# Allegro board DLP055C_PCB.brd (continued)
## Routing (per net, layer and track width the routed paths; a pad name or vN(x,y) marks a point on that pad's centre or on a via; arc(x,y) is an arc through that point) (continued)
P5V: length 223.8
  TOP w0.254: v1(177.87,5.34) 177.91,5.38 J28.1
  TOP w0.635: TP232.1 83.64,33.36 ; TP232.1 82.57,33.36 ; TP232.1 83.64,34.43 ; TP232.1 82.57,34.43
  LY3 w0.381: v1(177.91,4.49) 177.93,4.49 180.03,6.59 180.03,8.75 185.44,14.16 185.44,33.46 184.17,34.73 184.17,41.66 185.44,42.93 185.44,87.04 185.47,87.07 185.47,94.65 184.81,95.31 184.81,133.92 182.37,136.36 182.37,141.64 178.05,145.96 154.63,145.96 153.23,144.56 149.35,144.56 145.23,148.68 135.07,148.68 131.77,145.37 131.77,140.34 J67.1
  LY7_PLANE w0.635: J67.1 132.66,141.23 ; J67.1 132.66,139.44 ; J67.1 130.87,141.23 ; J67.1 130.87,139.44
  BOTTOM w0.381: C507.2 177.6,5.69 177.91,5.38 v1(177.87,5.34)
  BOTTOM w0.635: J60.1 129.15,9.6 ; J60.1 126.76,11.99 ; J60.1 129.15,11.99 ; J60.1 126.76,9.6 ; 82.57,33.36 TP232.1 ; TP232.1 82.57,34.43 ; TP232.1 83.64,33.36 ; TP232.1 83.64,34.43
  vias: v1(82.5,32.95) v1(83.77,32.95)
P5V_FP_FE: length 2.5
  TOP w0.445: 129.6,9.9 J60.2 131.39,9.9
P5V_VX1_FE: length 5.1
  TOP w0.445: 128.33,139.44 J67.2 ; J67.2 130.12,139.44 ; J67.2 130.12,141.23 ; J67.2 128.33,141.23
P12V: length 91.1
  TOP w0.381: 173.44,143.19 173.44,142.52 173.82,142.14 v1(174.47,142.14) ; 173.44,143.19 C1.1 ; 173.44,143.19 v1(174.47,143.19) ; 173.44,143.19 173.44,143.84 173.82,144.22 v1(174.47,144.22) ; 173.44,132.4 173.44,131.72 173.82,131.34 v1(174.47,131.34) ; 173.44,132.4 v1(174.47,132.4) ; 173.44,132.4 173.44,133.05 173.82,133.43 v1(174.47,133.43) ; 173.44,132.4 C8.1 172.71,132.4 172.26,132.85 170.63,132.85 169.34,131.56 169.34,130.41 168.15,129.22 R246.1 ; v1(139.09,41.91) R80.2 140.34,40.8 v1(140.41,40.73) ; v1(146.42,55.05) 145.75,54.38 J114.1
  LY7_PLANE w0.635: 172.26,136.38 J5.1 ; J5.1 174.45,138.57 ; J5.1 172.26,138.57 ; J5.1 174.45,136.38 ; 182.74,139.24 J8.1 ; J8.1 184.93,139.24 ; J8.1 184.93,141.43 ; J8.1 182.74,141.43 ; 172.26,147.18 J4.1 ; J4.1 174.45,149.37 ; J4.1 172.26,149.37 ; J4.1 174.45,147.18
  BOTTOM w0.254: U59.5 65.02,122.83 ; U59.3 65.24,123.83 ; U59.4 65.28,123.32
  BOTTOM w0.381: C71.1 183.2,140.97 J8.1 ; 147.76,53.97 147.65,53.86 C830.2 144.35,53.86 144.21,53.72
  BOTTOM w0.635: 137.63,51.68 J97.2 136.05,51.68 ; 77.15,140.46 TP247.1 ; TP247.1 78.22,140.46 ; TP247.1 77.15,139.39 ; C803.1 71.46,133.5 ; C803.1 71.46,130.66 ; C803.1 69.94,132.08 ; C803.1 72.99,132.08 ; 101.51,25.09 J120.2 ; 99.07,25.09 J120.1 99.07,26.98 ; 120.66,25.73 J121.1 120.66,27.61 ; C805.1 79.06,132.94 ; C805.1 79.06,129.9 ; C805.1 80.48,131.42 ; C805.1 77.63,131.42 ; C804.1 80.96,129.18 ; C804.1 82.39,127.66 ; C804.1 80.96,126.14 ; C804.1 79.54,127.66 ; C802.1 73.34,128.55 ; C802.1 74.77,127.03 ; C802.1 71.92,127.03 ; C802.1 73.34,125.5 ; 68.11,136.5 C58.1 ; C58.1 69.53,134.98 ; C58.1 69.53,138.02 ; C58.1 70.96,136.5 ; 123.1,25.73 J121.2
  vias: v1(74.13,132.89) v1(74.18,131.9) v1(75.73,132.82) v1(75.65,131.88) v1(150.18,147.95) v1(150.18,146.69) v1(150.18,145.41) v1(151.45,147.95) v1(151.45,146.69) v1(151.45,145.41) v1(152.72,147.95) v1(152.72,146.69) v1(152.72,145.41) v1(155.74,54.13) v1(156.79,54.21) v1(157.8,54.16) v1(158.79,54.13)
P12V_CNTL_D: length 7.8
  TOP w0.191: v1(61.39,133.84) 60.9,133.35 R825.1
  BOTTOM w0.191: v1(61.39,133.84) 61.33,133.78 R826.2 58.15,133.78 57.7,134.22 57.7,136.47 Q13.3
P12V_CNTL_G: length 29.3
  TOP w0.191: C809.2 52.24,138.49 v1(52.24,139.56) 52.18,139.62 R830.1 ; SW5.1 51.72,143.51 52.12,143.11 52.12,141.04 R830.1 ; R830.1 R824.1
  LY3 w0.122: v1(52.24,139.56) 48.59,135.9 v1(42.82,135.9)
  BOTTOM w0.191: D51.3 43.29,135.43 v1(42.82,135.9) ; D50.2 51.43,138.74 v1(52.24,139.56) 52.91,138.89 Q13.1
P12V_DLPA100: length 150.7
  TOP w0.203: v1(61.2,58.01) 61.28,58.01 61.49,57.8 U555.9 ; v1(69.89,99.79) 69.96,99.71 U557.9 ; U557.22 78.27,95.18 78.41,95.05 v1(78.41,94.98) ; U557.37 v1(80.01,105.41) ; v1(82.65,99.16) 82.36,99.16 82.3,99.21 U557.27 ; U555.22 69.38,53.72 69.39,53.71 69.39,52.72 69.38,52.71 69.38,52.16 69.1,51.88 v1(69.1,50.23) ; U555.27 v1(73.54,57.3) ; U556.42 28.44,55.95 28.44,56.77 28.32,56.89 28.32,57.56 v1(28.14,57.74) ; v1(22.26,50.47) 22.55,50.18 U556.9 ; U556.37 v1(31.81,55.88) ; v1(68.25,65.67) 67.88,65.3 67.88,65.13 67.87,65.12 67.87,64.7 67.88,64.69 U555.42 ; U557.42 76.77,106.57 v1(76.5,106.84) ; U555.37 v1(71.08,63.5)
  TOP w0.254: U556.22 v1(30.01,45.51) ; U556.27 v1(34,49.68)
  TOP w0.381: v1(69.1,50.23) 67.03,48.16 C752.2 ; DN7.2 v1(25.72,29.67) ; R781.2 32.82,42.48 v1(32.15,42.48) ; DN5.2 v1(28.89,29.67) ; R800.1 v1(87.65,98.99) ; R803.1 v1(66.29,105.34) ; DN8.2 v1(35.24,29.67) ; v1(84.93,94.4) 84.37,94.4 R802.2 ; DN2.2 v1(59.25,35.97) ; DN3.2 v1(45.59,36.36) ; DN4.2 v1(59.25,40.49) ; DN6.2 v1(32.07,29.67) ; v1(31.1,45.31) 31.1,44.3 C773.2 ; DN11.2 v1(73.63,91.12) ; C787.2 v1(80.24,91.82) ; DN1.2 v1(55.44,35.97)
  BOTTOM w0.254: U59.8 59.91,123.83 ; U59.6 59.69,122.83 ; U59.7 59.57,123.32
  BOTTOM w0.381: v1(28.14,57.74) 28.22,57.67 28.22,56.24 28.57,55.89 C774.2 ; R739.2 v1(81.13,55.51) ; v1(22.26,50.47) 22.65,50.09 C775.2 ; v1(76.5,106.84) 76.5,105.71 C789.2 ; C753.2 69.51,65.36 68.96,65.36 68.65,65.67 v1(68.25,65.67) ; C776.2 30.08,45.58 v1(30.01,45.51) ; v1(78.41,94.98) 78.66,94.98 78.74,95.06 C788.2
  BOTTOM w0.635: 49.07,35.11 TP249.1 ; TP249.1 49.07,36.18 ; TP249.1 50.14,35.11 ; TP249.1 50.14,36.18 ; 78.02,109.05 R801.1 ; R801.1 78.02,110.27 ; R801.1 77.29,109.66 ; R801.1 78.76,109.66 ; DN12.2 64.45,88.61 ; DN12.2 63.87,87.95 ; DN12.2 64.45,87.29 ; DN10.2 67.63,88.61 ; DN10.2 67.04,87.95 ; DN10.2 67.63,87.29 ; 57.47,128.73 C828.2 ; C828.2 57.47,129.95 ; C828.2 58.2,129.34 ; C828.2 56.73,129.34 ; C829.2 58.1,120.19 ; C829.2 58.84,119.58 ; C829.2 57.37,119.58 ; C829.2 58.1,118.97 ; 32.7,46.81 R779.1 ; R779.1 33.44,47.42 ; R779.1 32.7,48.03 ; R779.1 31.97,47.42 ; R782.1 27.72,60.53 ; R782.1 26.99,61.14 ; R782.1 26.99,59.92 ; R782.1 26.25,60.53 ; C823.1 61.43,99.09 ; C823.1 58.58,99.09 ; C823.1 60.01,97.56 ; 70.9,64.95 C753.2 69.92,64.07 ; 54.32,123.04 C824.1 ; C824.1 54.32,125.88 ; C824.1 52.79,124.46 ; C824.1 55.84,124.46 ; R780.1 29.63,60.53 ; R780.1 28.89,61.14 ; R780.1 28.89,59.92 ; R780.1 28.16,60.53 ; 61.1,127 C827.2 ; C827.2 62.32,127 ; C827.2 61.71,127.74 ; C827.2 61.71,126.26 ; DN9.2 70.8,88.61 ; DN9.2 70.8,87.29 ; DN9.2 70.22,87.95 ; 67,49.02 C755.2 ; C755.2 67.98,49.9 ; C755.2 68.96,49.02 ; C754.2 73.67,55.54 ; C754.2 72.69,56.42 ; C754.2 71.71,55.54 ; 66.36,97.56 C826.1 ; C826.1 64.93,99.09 ; C826.1 66.36,100.61 ; C826.1 67.78,99.09 ; 37.7,49.42 R778.2 ; R778.2 38.58,50.4 ; R778.2 37.7,51.38 ; 52.79,119.13 C821.1 ; C821.1 55.84,119.13 ; C821.1 54.32,117.7 ; C821.1 54.32,120.55 ; C775.2 25.03,50.09 ; 70.78,114.78 C825.1 ; C825.1 69.25,116.2 ; C825.1 70.78,117.63 ; C825.1 72.3,116.2 ; 30.08,48.21 C776.2 30.96,47.23 ; 78.74,97.5 C788.2 77.87,96.52 ; 85.83,100.15 R799.2 85.83,102.1 ; 81.13,57.82 R739.2 82,56.85 ; 52.79,129.79 C822.1 ; C822.1 55.84,129.79 ; C822.1 54.32,131.22 ; C822.1 54.32,128.37 ; 29.45,55.88 C774.2 28.57,54.9 ; C790.2 81.91,99.38 ; C790.2 80.93,98.5 ; C790.2 79.95,99.38 ; 77.68,105.41 C789.2 76.8,104.43
P12V_DRV: length 6
  TOP w0.381: U35.12 144.28,43.82 v1(144.11,43.99) 142.74,43.99 C133.1 R80.1
  BOTTOM w0.381: C320.1 144.87,43.84 144.26,43.84 v1(144.11,43.99)
P12V_REF: length 4.7
  TOP w0.191: v1(49.42,139.74) R823.1
  BOTTOM w0.191: D50.1 49.53,139.63 v1(49.42,139.74) R829.2
P12V_SEQ_EN: length 28
  LY3 w0.122: v1(66.45,124.04) 69.42,121.07 70.28,121.07 71.42,119.92 71.42,118.14 74.94,114.62 79.75,114.62 v1(80.65,113.72)
  BOTTOM w0.191: U58.4 v1(80.65,113.72) ; U59.2 64.7,124.33 64.99,124.61 65.87,124.61 v1(66.45,124.04) 66.46,124.03 R198.2
P12V_SW_G: length 9.7
  TOP w0.191: D49.1 58.56,133.38 R825.2 ; R825.2 R822.1 ; R825.2 58.53,132.13 57.7,131.3 57.7,129.99 Q12.G
P12V_VIN: length 30.9
  TOP w0.445: 43.57,129.62 J528.1 45.96,129.62 ; 42.79,129.62 J527.1 40.4,129.62 ; 66.46,119.92 TP245.1
  LY8_PLANE w0.376: J527.1 42.49,129.91 ; J527.1 40.7,131.71 ; J527.1 40.7,129.91 ; J527.1 42.49,131.71 ; J528.1 45.66,129.91 ; J528.1 43.87,131.71 ; J528.1 43.87,129.91 ; J528.1 45.66,131.71 ; TP245.1 67.53,118.84 ; TP245.1 67.53,119.92 ; TP245.1 66.46,119.92 ; TP245.1 66.46,118.84
  BOTTOM w0.381: U524.8 169.73,143.21 C811.2 172.33,143.08 C810.2 v1(172.4,144.45) ; R833.2 v1(171.97,132.16)
  BOTTOM w1.016: J527.1 J528.1
VBUS: length 13.6
  TOP w0.191: TP76.1 39.86,105.88 37.94,105.88 37.38,106.43 37.38,110.4 34.33,113.45 U26.65
VDD33_FPD: length 25.5
  TOP w0.305: v1(146.61,95.26) 146.51,95.26 145.46,94.22 145.46,88.12 145.84,87.74 145.84,86.22 145.97,86.09 146.26,86.09 v1(146.45,85.9) U15.L13
  TOP w0.381: U15.E14 v1(140.45,86.9) ; U15.E6 v1(140.45,78.9) ; U15.G6 v1(142.45,78.9) ; U15.E8 v1(140.45,80.9) ; U15.E12 v1(140.45,84.9) ; U15.E10 v1(140.45,82.9) ; U15.L11 v1(146.45,83.9)
  BOTTOM w0.305: L506.2 143.16,79.61 v1(142.45,78.9) C287.1 ; v1(140.45,80.9) C267.1 ; v1(140.45,86.9) C230.1 ; v1(140.45,82.9) C266.1 ; v1(140.45,84.9) C265.1 ; C289.1 v1(140.45,78.9) U15.E6 ; C170.2 v1(146.61,95.26) ; v1(146.45,85.9) C255.1
  BOTTOM w0.381: v1(146.45,83.9) C258.1
VDD115_FPD: length 35.8
  TOP w0.381: U15.J6 v1(144.45,78.9) ; v1(141.45,83.9) U15.F11 142.47,83.88 142.47,82.92 ; 142.47,82.92 142.48,82.92 142.95,82.46 144.01,82.46 v1(146.45,84.9) U15.L12 ; 142.47,82.92 U15.F9 v1(141.45,81.9) ; U15.F7 v1(141.45,79.9)
  LY3 w0.381: 142.19,79.9 v1(141.45,79.9) ; 142.19,79.9 142.32,79.77 143.58,79.77 v1(144.45,78.9) 146.76,81.21 v1(146.76,82.05) ; 142.19,79.9 142.19,81.16 v1(141.45,81.9)
  LY12 w0.229: 141.95,79.4 141.95,73.43
  LY12 w0.254: v1(142.04,72.05) 142.04,73.34 141.95,73.43 ; v1(141.45,79.9) 141.95,79.4
  BOTTOM w0.305: v1(141.45,81.9) C262.1 ; v1(146.45,84.9) C257.1 ; v1(141.45,79.9) C264.1 ; v1(141.45,83.9) C263.1 ; v1(146.76,82.05) C259.2 146.44,80.7 C284.1 ; C286.1 v1(144.45,78.9)
  BOTTOM w0.381: L505.1 v1(142.04,72.05)
VDD115_HSSI0_PLL: length 3.1
  TOP w0.191: U15.AE22 v1(161.45,95.9)
  BOTTOM w0.381: C155.1 v1(161.45,95.9) C159.1 L13.1
VDD115_HSSI1_PLL: length 3.4
  TOP w0.191: U15.AE10 v1(161.45,82.9)
  BOTTOM w0.381: L24.1 C239.1 C236.1 v1(161.45,82.9)
VDD115_PLLMA: length 3.4
  TOP w0.191: U15.AE18 v1(161.45,91.9)
  BOTTOM w0.381: v1(161.45,91.9) U15.AE18 C182.1 L16.1
VDD115_PLLMB: length 3.1
  TOP w0.191: U15.F15 v1(141.45,87.9)
  BOTTOM w0.381: C224.1 U15.F15 v1(141.45,87.9) C228.1
VDD115_PLLS: length 3.2
  TOP w0.191: U15.F16 v1(141.45,89.9)
  BOTTOM w0.305: C226.1 140.86,89.32 140.03,89.32 C229.1
  BOTTOM w0.381: L21.1 v1(141.45,89.9) C226.1
3D_LR: length 7.9
  TOP w0.191: J62.1 119.7,20.95 TP212.1 J61.2
3D_REF: length 142.7
  TOP w0.191: J44.3 89.15,8.65 89.15,8.65 89.15,9.07 89.15,9.07 v1(89.15,9.45)
  TOP w0.381: U15.D15 v1(139.45,87.9)
  LY3 w0.076: 137.3,88.52 137.09,88.52 137.08,88.53 136.93,88.53 136.93,88.52 136.65,88.52 136.62,88.49 136.28,88.49 136.24,88.52 135.99,88.52
  LY3 w0.102: v1(139.45,87.9) 139.45,87.96 138.89,88.52 137.3,88.52 ; 135.99,88.52 135.88,88.64
  LY3 w0.122: v1(91.26,87.45) 91.32,87.45 92.89,89.02 92.89,89.15 94.7,90.96 105.57,90.96 105.94,90.59 110.13,90.59 110.51,90.98 110.52,90.98 111.83,92.29 119.5,92.29 121.38,90.41 124.75,90.41 126.35,88.81 135.71,88.81 135.88,88.64
  LY12 w0.122: v1(91.26,87.45) 91.79,86.92 91.79,62.98 98.07,56.7 98.07,54.19 88.97,45.09 88.97,29.3 89.19,29.08 89.19,19.85 86.92,17.58 86.92,13.54 87.52,12.94 88.67,12.94 89.68,11.93 89.68,9.99 v1(89.15,9.45)
38MHZ_I: length 6.8
  BOTTOM w0.191: R118.1 C232.2 133.78,86.16 132.99,85.36 131.17,85.36 130.6,85.94 X2.1
38MHZ_O: length 3.9
  BOTTOM w0.191: X2.3 133.63,89.37 R117.1 133.78,89.96 C231.2
40MHZ_CLK0: length 227.2
  TOP w0.185: J500.26 v1(59.37,9.8)
  LY3 w0.122: v1(59.37,9.8) 59.37,7.28 60.07,6.59 75.59,6.59 76.91,5.27 134.16,5.27 136.75,7.86 136.75,12.11 137.54,12.9 137.54,15.02 138.53,16.01 138.53,17.26 144.67,23.4 154.53,23.4 156.76,21.17 170.56,21.17 174.93,25.54 174.93,27.69 176.5,29.27 176.5,30.44 182.39,36.33 182.39,43.16 184.93,45.7 184.93,86.23 185.02,86.32 185.02,88.95 v1(184.45,89.52)
  BOTTOM w0.191: R706.1 173.56,96.68 174.4,97.52 182.44,97.52 183.28,96.68 183.28,93.38 182.45,92.54 R669.2 182.45,89.49 182.8,89.14 184.07,89.14 v1(184.45,89.52)
40MHZ_I: length 2.5
  TOP w0.191: R30.1 C69.2 171.72,93.34 X1.1
40MHZ_O: length 6.1
  TOP w0.191: R31.1 C70.2 170.38,89.97 170.98,89.37 172.87,89.37 173.57,90.07 X1.3
40MHZ_Y0: length 2.7
  BOTTOM w0.191: R669.1 181.41,89.64 180.64,90.41 179.25,90.41 U503.3
40MHZ_Y1: length 4.3
  BOTTOM w0.191: R656.1 R655.1 171.58,92.08 171.88,91.78 U503.8
ACT_A_CIPO: length 22
  TOP w0.191: U51.3 123.2,29.16 123.06,29.02 119.3,29.02 118.99,28.7 118.97,28.7 118.95,28.69 107.16,28.69 J120.4
ACT_A_CLK: length 21.3
  TOP w0.191: J120.5 108.31,28.34 119.1,28.34 119.11,28.36 119.13,28.36 119.44,28.67 123.2,28.67 123.21,28.69 123.31,28.69 124.2,29.57 U51.5
ACT_A_COPI: length 22.6
  TOP w0.191: U51.2 122.7,29.87 122.36,29.52 119.32,29.52 118.84,29.04 106.02,29.04 J120.3
ACT_B_CIPO: length 18.7
  TOP w0.191: J120.8 112.12,27.66 119.38,27.66 119.39,27.67 119.41,27.67 119.73,27.99 123.49,27.99 123.5,28 123.6,28 123.61,28.01 124.12,28.01 124.13,28.03 124.79,28.03 125.7,28.94 U51.8
ACT_B_CLK: length 17.8
  TOP w0.191: J120.9 113.28,27.31 119.52,27.31 119.54,27.33 119.55,27.33 119.87,27.64 123.63,27.64 123.64,27.66 123.74,27.66 123.75,27.67 124.26,27.67 124.27,27.68 124.93,27.68 124.94,27.69 125.16,27.69 126.2,28.74 U51.9
ACT_B_COPI: length 19.1
  TOP w0.191: J120.7 110.97,28 119.24,28 119.25,28.01 119.27,28.01 119.59,28.33 123.34,28.33 123.36,28.34 123.46,28.34 123.47,28.36 123.97,28.36 124.7,29.08 124.7,29.38 124.68,29.4 124.68,29.82 124.7,29.84 U51.6
ACT_C_CIPO: length 5.2
  TOP w0.191: J121.4 127.7,28.27 U51.12
ACT_C_CLK: length 4.8
  TOP w0.191: U51.13 128.2,27.28 J121.5
ACT_C_COPI: length 5.6
  TOP w0.191: J121.3 125.28,27.35 125.3,27.35 126.55,28.6 126.55,28.62 127.2,29.27 U51.11
ACT_D_CIPO: length 5.5
  TOP w0.191: U51.16 129.7,29.06 J121.8
ACT_D_CLK: length 6.4
  TOP w0.191: U51.17 130.2,29.89 130.2,29.89 130.2,29.47 130.2,29.47 130.2,29.24 131.01,28.43 131.83,28.43 J121.9
ACT_D_COPI: length 5.3
  TOP w0.191: J121.7 128.7,28.56 U51.14
AFE_ARSTZ: length 124.5
  TOP w0.191: v1(113.69,9.65) 112.36,9.65 112.1,9.4 111.39,9.4 111.15,9.15 111.15,9.07 111.15,9.07 111.15,8.66 111.15,8.65 J44.47 ; v1(123.97,72.2) 124.76,71.41 126.74,71.41 127.4,72.07 132.36,72.07 133.03,72.74 138.34,72.74 138.49,72.89 141.09,72.89 141.54,73.34 144.98,73.34 145.49,73.85 145.49,74.91 145.95,75.37 U15.K2
  LY12 w0.122: v1(113.69,9.65) 113.69,11.72 113.18,12.23 110.38,12.23 109.52,13.09 109.52,15.66 108.12,17.06 99.82,17.06 98.24,18.63 98.24,28.08 102.34,32.17 102.34,55.88 104.67,58.22 107.12,58.22 108.27,59.37 108.27,69.65 109.77,71.15 119.06,71.15 120.55,72.63 122.8,72.63 123.23,72.2 v1(123.97,72.2)
AFE_CLK: length 101.1
  TOP w0.185: J44.44 109.65,9.25 109.94,9.55
  TOP w0.191: 109.94,9.55 110.25,9.55 v1(110.35,9.65) ; R626.2 v1(142.43,64.94)
  LY5 w0.122: v1(142.43,64.94) 143.15,64.22 145.59,64.22 148,61.81 148,56.6 150.19,54.42 152.4,54.42 154.59,52.23 154.59,31.23 150.9,27.54 143.07,27.54 134.16,18.63 117.67,18.63 115.97,16.93 113.71,16.93 112.11,15.32 112.11,12.81 111.81,12.51 111.81,10.17 111.29,9.65 v1(110.35,9.65)
AFE_CLK_T: length 13.1
  TOP w0.191: v1(142.32,65.85) 142.18,65.99 R626.1 ; U15.K3 v1(145.45,75.9)
  LY12 w0.122: v1(142.32,65.85) 142.41,65.95 142.41,66 143.43,67.01 143.43,70.16 145.13,71.87 145.13,72.91 145.44,73.21 145.44,75.89 v1(145.45,75.9)
AFE_IRQ: length 92.8
  TOP w0.191: R627.1 158.43,15.33 155.9,17.87 143.2,17.87 v1(142.82,17.48)
  TOP w0.381: U15.K4 v1(145.45,76.9)
  LY12 w0.122: v1(142.82,17.48) 142.82,22.43 151.38,31 151.38,36.64 150.87,37.14 146.83,37.14 145.99,37.99 145.99,39.62 145.73,39.87 142.55,39.87 142.09,40.33 142.09,41 142.4,41.31 142.4,41.88 140.84,43.44 140.84,48.83 140.82,48.85 140.82,52.75 140.84,52.77 140.84,60.59 141.23,60.98 141.23,65.66 142.59,67.01 142.59,69.76 144.04,71.21 144.04,72.73 144.98,73.67 144.98,76.44 145.44,76.9 v1(145.45,76.9)
AISEN: length 2.7
  TOP w0.191: U35.3 152.38,42.52 152.38,42.52 v1(152.46,42.52)
  BOTTOM w0.191: v1(152.46,42.52) 151.36,42.52 R144.1
ALF_CSYNC: length 111.3
  TOP w0.191: J44.42 108.61,7.64 108.61,9.26 109.36,10.01 109.94,10.01 110.73,10.79 TP51.1
  TOP w0.381: U15.J2 v1(144.45,74.9)
  LY5 w0.122: v1(144.45,74.9) 145.07,74.28 145.07,71.88 143.61,70.43 143.61,68.4 142.4,67.19 142.26,67.19 141.83,66.76 141.83,63.94 144.27,61.5 145,61.5 147.52,58.99 147.52,56.45 150.36,53.6 152.29,53.6 154.29,51.61 154.29,31.72 150.57,28 143.02,28 134.31,19.29 117.09,19.29 115.49,17.69 113.76,17.69 111.78,15.71 111.78,14.45 111.83,14.4 111.83,13.47 110.81,12.45 TP51.1
ALF_HSYNC: length 113.6
  TOP w0.191: TP52.1 108.15,10.04 J44.41
  TOP w0.381: U15.J1 v1(144.45,73.9)
  LY5 w0.122: TP52.1 108.9,12.6 109.72,13.42 109.72,15.29 110.59,16.16 110.59,20.91 112.49,22.82 129.2,22.82 130.92,24.55 138.58,24.55 142.67,28.63 150.31,28.63 152.95,31.27 152.95,50.56 151.18,52.33 149.96,52.33 146.35,55.94 146.35,57.06 143.91,59.5 142.79,59.5 141.75,60.54 141.75,62.65 141.45,62.95 141.45,67.06 142.16,67.78 142.16,70.8 141.37,71.59 141.37,72.43 141.67,72.74 143.84,72.74 144.45,73.34 v1(144.45,73.9)
ALF_VSYNC: length 121.5
  TOP w0.191: J44.40 107.65,8.96 107.65,8.96 107.65,9.38 107.65,9.38 107.65,10.15 TP53.1
  TOP w0.381: U15.K5 v1(145.45,77.9)
  LY5 w0.122: TP53.1 107,15.11 106.42,15.68 102.79,15.68 101.82,14.72 101.82,12.35 101.44,11.97 97.66,11.97 96.87,12.76 96.87,14.99 98.42,16.54 98.42,24.16 97.71,24.88 97.71,41.59 109.19,53.07 118.36,53.07 123.36,58.07 127.76,58.07 130.15,60.46 130.15,66.63 131.75,68.23 131.75,71.31 134.22,73.78 134.22,76.27 134.72,76.77 134.95,76.77 135.58,77.4 144.95,77.4 v1(145.45,77.9)
AW0_DAC_ENZ: length 16.1
  TOP w0.191: U51.30 131.2,36.57 130.98,36.36 v1(129.26,36.36)
  BOTTOM w0.191: TP208.1 120.75,35.98 126.77,35.98 127.3,35.45 R654.1 R653.1 129.22,36.32 v1(129.26,36.36)
AW1_DAC_ENZ: length 13
  TOP w0.191: v1(131.7,36.16) 131.7,37.03 131.7,37.03 131.7,37.45 131.7,37.45 U51.29
  LY3 w0.122: TP210.1 135.33,36.58 132.13,36.58 v1(131.7,36.16)
  BOTTOM w0.191: R651.1 132.21,38.21 131.64,37.65 131.64,36.22 v1(131.7,36.16) 131.72,36.14 131.72,35.59 131.57,35.45 R652.1
AW_DAC_ENZ: length 11.6
  TOP w0.191: v1(133.07,36.1) 138.07,36.1 138.43,35.75 U55.4
  BOTTOM w0.191: v1(133.07,36.1) 133.07,34.81 132.63,34.38 131.16,34.38 R652.2 R653.2
AWC0_DACCLK_0_1: length 71.1
  TOP w0.191: U15.AE2 v1(161.45,74.9) ; U51.40 126.2,39.8 126.34,39.94 126.34,41.49 126.39,41.54 ; J110.3 129.68,41.73 126.58,41.73 126.39,41.54 ; 126.39,41.54 124.63,41.54 124.2,41.11 124.2,41.09 124.2,41.09 124.2,40.67 124.2,40.67 124.2,40.42 124.2,40.42 124.2,40 124.2,40 U51.44
  LY3 w0.122: J110.3 133.89,45.95 140.09,45.95 142.9,48.75 148.94,48.75 149.98,49.79 149.98,51.32 149.65,51.65 v1(148.97,51.65)
  LY12 w0.122: v1(161.45,74.9) 161.9,74.45 161.9,73.56 161.54,73.2 161.54,72.76 161.56,72.74 161.56,71.9 161.54,71.88 161.54,71.22 161.26,70.94 161.26,66.1 161.67,65.69 161.67,60.51 161.06,59.9 157.27,59.9 156.98,59.61 156.98,57.13 151.5,51.65 v1(148.97,51.65)
AWC0_DACD_PWMB_0: length 68.2
  TOP w0.191: U51.47 122.7,41.69 124.28,43.27 126.13,43.27 J110.5 ; U15.AD4 v1(160.45,76.9)
  LY3 w0.122: v1(148.27,50.76) 148.27,49.76 147.79,49.27 142.68,49.27 140.09,46.68 129.55,46.68 J110.5
  LY12 w0.076: v1(160.45,76.9) 160.03,76.49 160.03,74.25
  LY12 w0.102: 160.03,74.25 159.96,74.17 159.96,73.68
  LY12 w0.122: v1(148.27,50.76) 148.2,50.83 148.2,52.01 148.89,52.71 151.77,52.71 155.37,56.31 155.37,60.71 156.33,61.67 156.33,62.09 159.23,64.99 159.23,69.63 158.13,70.73 158.13,71.28 158.42,71.57 158.42,72.14 159.96,73.68
  BOTTOM w0.191: v1(148.27,50.76) R135.2
AWC0_DACD_PWMB_1: length 90.7
  TOP w0.191: U51.43 v1(124.7,40.88) ; U15.AD2 v1(160.45,74.9)
  LY3 w0.122: v1(124.7,40.88) 124.7,39.16 125.88,37.98 134.34,37.98 136.74,40.39 138.87,40.39 139.16,40.09 152.12,40.09 154.38,42.35 154.38,42.5 158.24,46.36 158.95,46.36 159.93,47.35 163.72,47.35 165.38,49.01 165.38,50.28 v1(165.35,50.3)
  LY12 w0.122: v1(124.7,40.88) 124.7,41.98 J110.7
  BOTTOM w0.191: v1(165.35,50.3) 164.92,50.73 164.92,51.59 164.94,51.61 164.94,57.47 162.68,59.73 158.36,59.73 157.98,60.11 157.85,60.11 156.41,61.55 156.41,64.32 160.09,68 160.09,69.63 160.42,69.96 161.29,69.96 161.57,70.24 161.57,72.98 160.96,73.59 160.96,74.38 160.45,74.89 v1(160.45,74.9)
AWC0_DACS_PWMA_0: length 73.7
  TOP w0.191: U15.AF4 v1(162.45,76.9) ; U51.46 123.2,40 123.2,40 123.2,40.42 123.2,40.42 123.2,41.17 124.41,42.38 127.78,42.38 J110.4
  LY3 w0.122: v1(149.22,50.76) R134.2 148.19,49.01 142.79,49.01 140.11,46.34 131.75,46.34 J110.4
  LY12 w0.122: v1(162.45,76.9) 162.01,76.46 162.01,75.64 162.41,75.24 162.41,73.4 162.35,73.34 162.35,71.24 161.82,70.71 161.82,67.01 163.7,65.13 163.7,60.28 161.72,58.3 161.72,53.69 161.71,53.68 161.71,53.22 161.26,52.76 153.01,52.76 151,50.76 v1(149.22,50.76)
  BOTTOM w0.191: v1(149.22,50.76) R134.2
AWC0_DACS_PWMA_1: length 93.7
  TOP w0.191: U15.AD3 v1(160.45,75.9) ; v1(125.6,40.93) 125.9,40.62 125.9,40.09 125.7,39.89 U51.41
  LY3 w0.122: v1(167.15,52.41) 165.3,52.41 164.59,51.7 164.59,50.71 164.03,50.15 164.03,48.95 162.68,47.61 159.05,47.61 158.34,46.9 157.88,46.9 151.71,40.73 144.01,40.73 143.28,41.46 140.18,41.46 139.37,40.65 136.52,40.65 134.13,38.26 127.38,38.26 126.59,39.05 126.58,39.05 126.46,39.17 126.46,40.06 v1(125.6,40.93)
  LY12 w0.122: v1(125.6,40.93) 125.6,43.63 J110.6
  BOTTOM w0.191: v1(167.15,52.41) 166.65,51.9 165.76,51.9 165.4,52.26 165.4,57.05 165.4,57.05 165.4,57.62 162.82,60.2 158.37,60.2 158.12,60.45 157.99,60.45 156.75,61.69 156.75,64.16 161.95,69.35 161.95,70.9 162.25,71.21 162.25,75.22 162.09,75.38 161.02,75.38 160.5,75.9 v1(160.45,75.9)
AWC0_OUT_ENZ: length 102.1
  TOP w0.191: U15.AE3 v1(161.45,75.9) ; v1(126.26,35.19) 134.39,35.19 136.37,33.21 136.37,32.46 U55.1
  LY3 w0.122: J110.2 134.94,44.6 136.01,45.68 140.19,45.68 143.01,48.49 149.32,48.49 151.59,50.76 158.41,50.76 160.65,48.52 162.43,48.52 163.27,49.36 163.27,54.51 162.43,55.36 158.64,55.36 157.63,56.37 v1(157.63,59.27)
  LY12 w0.122: v1(161.45,75.9) 161.79,75.56 161.79,75.28 162.13,74.94 162.13,73.4 162.07,73.34 162.07,71.36 161.54,70.82 161.54,66.73 162.71,65.57 162.71,60.51 160.88,58.68 158.21,58.68 v1(157.63,59.27)
  BOTTOM w0.191: J110.2 133.22,42.73 133.22,39.86 133.9,39.18 133.9,34.83 132.61,33.54 127.48,33.54 127.32,33.7 R654.2 126.46,34.4 126.26,34.6 v1(126.26,35.19)
AWC0_PWMA_0: length 11.5
  TOP w0.191: U35.16 v1(146.74,41.22)
  BOTTOM w0.191: R134.1 149.22,45.1 149.77,44.55 149.77,42.7 148.3,41.22 v1(146.74,41.22)
AWC0_PWMB_0: length 12.6
  TOP w0.191: U35.15 144.42,41.87 v1(144.11,41.56)
  BOTTOM w0.191: R135.1 148.27,44.27 147.72,43.72 147.72,43.2 148,42.92 148,42.38 147.41,41.78 146.04,41.78 145.81,41.56 v1(144.11,41.56)
AWC1_DACCLK_0_1: length 81
  TOP w0.191: 130.2,40.93 130.02,41.11 128.27,41.11 v1(128.2,41.04) 128.2,40.44 128.2,40.44 128.2,40.02 128.2,40.02 U51.36 ; 130.2,40.93 131.63,42.35 135.53,42.35 136.19,43.01 136.19,45.65 138.78,48.24 146.94,48.24 147.32,48.63 v1(147.32,50.76) ; 130.2,40.93 U51.32 ; U15.AC5 v1(159.45,77.9)
  LY3 w0.122: v1(128.2,41.04) 128.2,41.53 127.73,42 117.62,42 117.22,42.4 117.22,44.39 J110.9
  LY12 w0.076: 159.86,77.49 159.86,74.64 159.61,74.39
  LY12 w0.102: v1(159.45,77.9) 159.86,77.49 ; 158.87,73.34 158.94,73.41 158.94,74.15 159.17,74.39 159.61,74.39
  LY12 w0.122: v1(147.32,50.76) 147.32,51.82 148.52,53.02 148.88,53.02 150.53,54.67 153.33,54.67 154.97,56.31 154.97,60.71 156.05,61.79 156.05,62.21 158.95,65.1 158.95,69.5 157.78,70.67 157.78,71.36 158.07,71.65 158.07,72.54 158.87,73.34
AWC1_DACD_PWMB_0: length 83.5
  TOP w0.191: U51.38 127.2,40.02 127.2,40.02 127.2,40.44 127.2,40.44 v1(127.2,41.06) ; U15.AC2 v1(159.45,74.9)
  LY3 w0.122: v1(144.22,46.54) 143.58,46.54 140.35,43.31 140.35,42 139.26,40.91 136.41,40.91 134.06,38.55 128.15,38.55 127.2,39.5 v1(127.2,41.06) 126.23,41.06 125.83,41.46 115.72,41.46 114.35,42.83 113.69,42.83 J110.11
  LY12 w0.122: v1(159.45,74.9) 159.32,74.9 158.85,74.42 158.12,74.42 157.76,74.06 157.76,71.74 157.41,71.4 157.41,70.63 158.67,69.38 158.67,65.22 155.77,62.32 155.77,61.91 154.66,60.79 154.66,58.99 153.79,58.12 149.25,58.12 149.15,58.03 149.13,58.03 148.62,57.51 148.62,57.48 148.61,57.47 148.61,56.83 148.62,56.82 148.62,56.79 149.13,56.27 149.16,56.27 149.64,55.8 149.64,54.17 148.77,53.3 148.18,53.3 145.97,51.08 145.74,51.08 v1(145.41,50.76)
  BOTTOM w0.191: v1(145.41,50.76) R137.2 144.53,50.05 144.22,49.74 v1(144.22,46.54)
AWC1_DACD_PWMB_1: length 110.6
  TOP w0.191: U15.AD5 v1(160.45,77.9) ; v1(128.76,40.22) 128.7,40.17 U51.35
  LY3 w0.122: v1(156.45,47.77) 155.42,46.74 149.75,46.74 148.85,47.65 143.34,47.65 142.75,47.06 142.75,46.96 138.34,42.55 137.31,42.55 133.99,39.23 128.95,39.23 128.7,39.48 128.7,40.17 v1(128.76,40.22) 128.7,40.27 128.7,41.58 128.02,42.26 118.63,42.26 118.21,42.68 118.21,44.09 118.23,44.11 118.23,45.45 117.62,46.06 111.78,46.06 110.89,45.17 110.89,43.34 110.36,42.81 108.64,42.81 J110.13
  LY12 w0.076: 160.86,76.31 160.86,73.36 160.84,73.34
  LY12 w0.102: v1(160.45,77.9) 160.48,77.9 160.97,77.42 160.97,76.42 160.86,76.31
  LY12 w0.122: 160.84,73.34 160.84,72.68 161.01,72.51 161.01,72.12 160.73,71.85 160.72,71.85 160.27,71.4 160.27,70.92 160.23,70.88 160.23,70.84 160.21,70.81 160.21,70.43 160.23,70.4 160.23,65.95 160.63,65.56 160.63,60.71 160.22,60.31 157.22,60.31 156.57,59.66 156.57,57.12 151.81,52.36 148.94,52.36 148.48,51.9 148.48,51.34 148.75,51.07 148.75,50.57 149.03,50.29 153.93,50.29 v1(156.45,47.77)
AWC1_DACS_PWMA_0: length 85.3
  TOP w0.191: U51.37 v1(127.7,40.23) ; U15.AC4 v1(159.45,76.9)
  LY3 w0.122: J110.10 115.79,43.27 115.79,42.55 116.62,41.73 127.47,41.73 127.7,41.49 v1(127.7,40.23) 127.7,39.61 128.36,38.96 134.09,38.96 137.42,42.28 138.64,42.28 v1(143.28,46.92)
  LY12 w0.122: v1(159.45,76.9) 158.94,76.39 158.94,75.69 158.69,75.44 158.06,75.44 157.76,75.14 157.76,74.5 157.48,74.23 157.48,71.94 157.12,71.58 157.12,70.62 157.13,70.61 157.13,69.21 158.34,68 158.34,65.29 155.49,62.44 155.49,62.02 154.38,60.9 154.38,59.67 153.11,58.4 149.37,58.4 149.13,58.4 149.04,58.31 149.01,58.31 148.34,57.63 148.34,57.59 148.33,57.59 148.33,56.71 148.34,56.71 148.34,56.67 149.01,55.99 149.05,55.99 149.36,55.68 149.36,54.29 148.65,53.58 148.07,53.58 145.9,51.41 145.32,51.41 144.93,51.02 144.93,50.56 145.23,50.26 145.87,50.26 v1(146.37,50.76)
  BOTTOM w0.191: v1(143.28,46.92) 143.28,50.2 144.5,51.42 145.71,51.42 v1(146.37,50.76) R136.2
AWC1_DACS_PWMA_1: length 87.7
  TOP w0.191: U15.AC1 159.43,73.92 159.43,73.39 160.01,72.81 160.01,71.59 160.04,71.56 160.04,68.59 159.76,68.3 158.76,68.3 158.75,68.3 158.56,68.3 158.54,68.28 158.31,68.28 157.68,67.65 157.68,65.57 155.63,63.52 155.63,60.24 157.22,58.66 157.22,55.99 156.21,54.97 154.4,54.97 153.62,54.19 v1(153.62,49.67) ; U51.33 129.7,39.77 129.56,39.91 v1(129.56,40.32)
  LY3 w0.122: v1(153.62,49.67) 152.24,48.29 149.88,48.29 149.55,47.97 143.29,47.97 143.23,47.91 143.23,47.91 142.49,47.17 142.49,47.07 138.23,42.81 136.98,42.81 133.75,39.58 129.76,39.58 129.56,39.79 v1(129.56,40.32) 129.56,41.84 128.77,42.63 119.07,42.63 118.49,43.21 118.49,43.98 118.5,44 118.5,45.56 118.49,45.57 118.49,46.06 118.06,46.49 111.58,46.49 J110.12
AWC1_OUT_ENZ: length 111.4
  TOP w0.191: v1(131.85,40.27) 132.71,41.13 134.64,41.13 135.25,40.52 135.25,37.37 135.89,36.74 138.93,36.74 139.62,36.05 139.62,31.53 139.04,30.95 138.02,30.95 137.48,31.49 U55.2 ; U15.AD1 v1(160.45,73.9)
  LY3 w0.122: v1(156.03,58.07) 156.76,58.81 156.76,59.39 157.12,59.75 157.91,59.75 158.8,58.86 163.32,58.86 164.33,57.84 164.33,52.43 163.6,51.7 163.6,49.31 162.24,47.95 160.41,47.95 157.93,50.43 151.63,50.43 149.43,48.23 143.18,48.23 143.13,48.17 143.12,48.17 142.23,47.28 142.23,47.23 138.23,43.23 134.81,43.23 v1(131.85,40.27) 129,43.11 121.03,43.11 J110.8
  LY12 w0.122: v1(160.45,73.9) 160.45,73.01 160.07,72.63 160.07,72.04 160,71.97 160,71.03 159.62,70.66 159.62,60.85 159.36,60.59 157.11,60.59 156.03,59.51 v1(156.03,58.07)
  BOTTOM w0.191: R651.2 132.4,39.72 v1(131.85,40.27)
AWC1_PWMA_0: length 4.7
  TOP w0.191: U35.9 146.57,45.77 v1(146.75,45.95)
  BOTTOM w0.191: v1(146.75,45.95) 146.37,46.33 R136.1
AWC1_PWMB_0: length 5.7
  TOP w0.191: v1(143.93,45.62) 143.94,45.62 144.44,45.12 U35.10
  BOTTOM w0.191: v1(143.93,45.62) 144.26,45.95 144.41,45.95 145.41,46.95 R137.1
BALLAST_CNTL_PWR: length 3.1
  TOP w0.191: J27.3 182.14,20.32 v1(184.16,20.32)
  BOTTOM w0.191: R528.2 v1(184.16,20.32)
BISEN: length 2.6
  TOP w0.191: U35.6 v1(152.45,44.47)
  BOTTOM w0.191: v1(152.45,44.47) 152.38,44.47 152.38,44.48 151.22,44.48 R133.1
BT656_CLK: length 186.1
  TOP w0.185: J500.10 v1(51.37,9.83) ; J44.26 v1(100.65,9.75)
  TOP w0.191: v1(135.61,69.83) 135.61,71.03 136.57,71.99 138.58,71.99 138.98,71.59 140.86,71.59 141.19,71.91 141.19,72.4 141.75,72.96 145.41,72.96 145.95,73.49 U15.K1
  LY3 w0.122: v1(100.65,9.75) 100.63,9.77 100.63,11.18 99.18,12.63 91.79,12.63 90.49,13.94 J43.12 90.45,13.97 89.18,15.25 84.54,15.25 78.21,8.92 74.62,8.92 73.73,9.81 71.22,9.81 69.38,11.65 68.54,11.65 68.05,11.15 68.05,11.11 67.81,10.88 57.73,10.88 56.38,9.53 56.38,8.5 55.8,7.91 51.94,7.91 51.38,8.47 51.38,9.82 v1(51.37,9.83)
  LY12 w0.122: v1(135.61,69.83) 135.61,68.23 134.34,66.96 134.34,63.76 134.51,63.59 134.51,55.03 138.35,51.19 138.35,47.71 136.22,45.58 136.22,41.44 135.05,40.27 135.05,32.62 139.32,28.36 139.32,25.38 138.71,24.77 131.7,24.77 123.36,16.44 123.36,12.86 122.73,12.23 122.73,9.58 123.14,9.18 123.14,4 122.47,3.34 108.48,3.34 102.06,9.75 v1(100.65,9.75)
BT656_DATA_0: length 182.3
  TOP w0.191: J44.38 106.61,7.64 106.61,9.66 105.89,10.38 105.89,11.13 106.57,11.81 113.73,11.81 J43.2 ; U15.N4 v1(149.45,76.9) ; R537.2 R536.2 v1(60.01,12.78)
  LY3 w0.122: v1(60.01,12.78) 60.01,13.26 60.75,14 61.48,14 62.71,12.78 64.55,12.78 65.21,13.43 65.98,13.43 66.69,12.72 67.02,12.72 68.07,13.77 68.07,14.06 69.25,15.24 79.84,15.24 81.14,16.53 113.33,16.53 J43.2
  LY5 w0.122: J43.2 119.12,17.2 127.25,17.2 129.46,14.99 132.84,14.99 134.59,16.75 135.48,16.75 143.2,24.47 153.21,24.47 155.9,27.16 155.9,44.87 158.37,47.33 158.37,52.36 159.64,53.63 159.64,54.95 156.8,57.78 156.8,62.38 154.11,65.08 154.11,70.23 152.66,71.67 150.8,71.67 150.17,72.29 150.17,75.21 149.98,75.4 149.98,76.35 149.99,76.36 v1(149.45,76.9)
BT656_DATA_0_M: length 3.5
  TOP w0.185: J500.24 58.37,10.54 R537.1
BT656_DATA_0_S: length 3.5
  TOP w0.185: J500.28 60.37,10.54 R536.1
BT656_DATA_1: length 188.6
  TOP w0.191: U15.N5 v1(148.45,77.9) ; R535.2 v1(61.28,13.3) 61.01,13.57 57.68,13.57 57.48,13.37 57.48,11.96 R538.2 ; R549.1 v1(144.02,65.93) ; J44.37 106.15,9.51 105.35,10.31 105.35,11.35 106.19,12.2 111.58,12.2 J43.3
  LY3 w0.122: v1(61.28,13.3) 62.15,12.43 67.2,12.43 68.4,13.62 68.4,14 69.36,14.97 80.51,14.97 81.81,16.26 100.71,16.26 101.37,15.6 111.65,15.6 113.29,13.97 J43.3
  LY5 w0.122: v1(144.02,65.93) 144.45,65.49 147.98,65.49 148.99,64.47 153.62,64.47 155.01,63.08 155.01,53.31 155.67,52.65 155.67,50.54 155.01,49.88 155.01,30.49 151.43,26.91 143.71,26.91 135,18.2 118.39,18.2 116.63,16.44 114.04,16.44 113.35,15.75 J43.3
  LY12 w0.122: v1(144.02,65.93) 144.02,65.92 145.31,65.92 146.53,67.14 146.53,72.14 145.94,72.73 145.94,78.04 146.35,78.44 147.9,78.44 148.44,77.9 v1(148.45,77.9)
BT656_DATA_1_M: length 3.3
  TOP w0.185: J500.22 57.37,10.81 R538.1
BT656_DATA_1_S: length 3.3
  TOP w0.185: J500.30 61.37,10.81 R535.1
BT656_DATA_2: length 181.2
  TOP w0.185: J500.46 v1(69.37,9.65)
  TOP w0.191: U15.M1 147.95,73.14 147.32,72.51 147.32,71.51 147.53,71.3 147.54,71.3 147.71,71.12 147.71,68.58 147.63,68.5 147.63,68.48 147.05,67.9 v1(145.79,67.9) ; J43.4 109.38,12.54 105.29,12.54 104.71,11.96 104.71,10.41 105.65,9.47 105.65,9.36 105.65,9.36 105.65,8.94 105.65,8.94 J44.36
  LY3 w0.122: J43.4 110.81,13.92 109.47,12.58 105.69,12.58 101.5,8.39 69.6,8.39 69.36,8.63 69.36,9.64 v1(69.37,9.65) ; v1(145.79,67.9) 145.25,67.9 144.93,68.22 138.29,68.22 136.21,70.31 135.69,70.31 134.87,71.13 128.49,71.13 127.53,70.16 127.53,68.36 126.62,67.45 120.51,67.45 119.53,68.44 v1(119.53,69.02)
  LY12 w0.122: v1(119.53,69.02) 117.75,70.8 109.98,70.8 108.56,69.38 108.56,59.06 107.01,57.51 104.8,57.51 102.84,55.56 102.84,31.84 98.57,27.57 98.57,19.95 100.78,17.74 108.81,17.74 110.81,15.74 J43.4
BT656_DATA_3: length 152
  TOP w0.185: J500.44 v1(68.37,9.65)
  TOP w0.191: U15.M2 147.95,75.37 147.49,74.91 147.49,73.36 146.66,72.53 146.66,71.99 146.3,71.64 144.4,71.64 143.45,72.59 141.87,72.59 141.54,72.26 141.54,71.55 141.75,71.33 142.76,71.33 142.97,71.12 142.97,68.61 142.62,68.26 141.42,68.26 140.71,67.55 v1(140.18,67.55) ; J43.5 107.18,12.88 105.15,12.88 104.36,12.1 104.36,10.27 105.15,9.49 v1(105.15,9.15) J44.35
  LY3 w0.122: v1(105.15,9.15) 105.15,8.54 104.72,8.11 68.93,8.11 68.4,8.64 68.4,9.63 v1(68.37,9.65)
  LY5 w0.122: J43.5 108.27,21.97 110.38,24.09 129.59,24.09 131.06,25.56 138.43,25.56 141.35,28.48 141.35,37.27 142.06,37.98 142.06,56.4 140.18,58.28 v1(140.18,67.55)
BT656_DATA_4: length 152.7
  TOP w0.185: J44.34 104.65,9.5
  TOP w0.191: J43.6 104.02,12.26 104.02,10.13 104.65,9.5 ; U15.M4 v1(147.45,76.9)
  LY5 w0.122: J43.6 105.73,12.07 103.25,9.58 103.25,8.31 103.81,7.76 116.84,7.76 117.8,8.72 130.45,8.72 132.2,6.97 155.35,6.97 160.02,11.63 160.02,44.47 159.28,45.2 159.28,47.3 158.8,47.79 158.8,51.77 160.02,52.99 160.02,55.33 157.07,58.27 157.07,69.79 157.17,69.89 157.17,71.26 157.45,71.54 157.45,74.81 156.99,75.28 156.99,77.17 156.75,77.4 147.95,77.4 v1(147.45,76.9)
BT656_DATA_5: length 156.9
  TOP w0.191: J43.7 103.19,12.52 103.65,12.07 103.65,9.3 103.65,9.3 103.65,8.88 103.65,8.88 J44.32 ; U15.M5 v1(147.45,77.9)
  LY5 w0.122: v1(147.45,77.9) 147.97,78.42 157.66,78.42 157.92,78.16 157.92,70.25 157.35,69.68 157.35,61.02 158.49,59.88 158.49,58.25 160.47,56.27 160.47,52.99 159.26,51.78 159.26,49.85 159.56,49.55 159.56,45.31 160.35,44.52 160.35,10.25 155.27,5.17 103.45,5.17 102.54,6.08 102.54,10.22 103.19,10.87 J43.7
BT656_DATA_6: length 105.5
  TOP w0.191: J43.8 103.15,11.47 J44.31 ; U15.L2 v1(146.45,74.9)
  LY5 w0.122: v1(146.45,74.9) 145.93,75.42 143.2,75.42 142.95,75.17 142.95,73.52 142.67,73.24 137.69,73.24 136.24,71.79 136.24,68 134.84,66.61 134.84,62.77 130.72,58.65 130.72,55.05 127.81,52.13 109.99,52.13 102.28,44.42 102.28,29.9 102.16,29.78 102.15,29.78 98.83,26.46 98.83,25.08 100.1,23.81 100.1,21.75 100.65,21.2 J43.8
BT656_DATA_7: length 107.9
  TOP w0.191: U15.L3 v1(146.45,75.9) ; J43.9 99.66,12.42 101.33,12.42 102.65,11.11 J44.30
  LY5 w0.122: v1(146.45,75.9) 145.96,76.39 135.96,76.39 135.73,76.16 135.73,74.63 134.44,73.34 134.44,73.01 132.02,70.59 132.02,68.12 131.36,67.46 131.36,65.97 130.45,65.06 130.45,60.21 127.85,57.61 123.66,57.61 118.73,52.68 109.19,52.68 97.98,41.47 97.98,25.13 99.31,23.8 99.31,16.59 98.11,15.39 J43.9
BT656_DATA_8: length 165.4
  TOP w0.185: v1(53.15,9.8) 53.15,9.37 53.37,9.15 J500.14
  TOP w0.191: J44.29 102.15,10.9 101.08,11.96 97.57,11.96 J43.10 ; U15.L4 v1(146.45,76.9)
  LY3 w0.122: J43.10 95.48,13.97 93.46,16 84.36,16 79.39,11.02 79.39,10.85 78.81,10.27 76.78,10.27 73.83,13.22 69.77,13.22 68.88,12.32 68.46,12.32 68.03,11.88 57.06,11.88 56.84,11.67 55.01,11.67 v1(53.15,9.8)
  LY5 w0.122: J43.10 96.6,15 96.6,15.11 98.15,16.66 98.15,24.05 97.44,24.76 97.44,41.91 108.87,53.34 118.25,53.34 123.56,58.66 127.95,58.66 129.82,60.52 129.82,66.69 131.34,68.22 131.34,71.59 133.19,73.43 133.19,78.11 133.47,78.39 145.84,78.39 145.94,78.29 145.94,77.45 146.45,76.95 v1(146.45,76.9)
BT656_DATA_9: length 171.3
  TOP w0.185: J500.12 v1(52.37,9.96)
  TOP w0.191: U15.L5 v1(146.45,77.9) ; J43.11 94.53,12.47 96.02,12.47 96.89,11.61 100.7,11.61 101.65,10.66 101.65,9.29 101.65,9.28 101.65,8.87 101.65,8.87 J44.28
  LY3 w0.122: J43.11 93.03,14.14 91.46,15.71 84.62,15.71 78.65,9.74 76.17,9.74 73.86,12.05 68.57,12.05 68.14,11.62 57.65,11.62 55.37,9.33 55.37,8.66 54.89,8.18 52.71,8.18 52.37,8.52 v1(52.37,9.96)
  LY5 w0.122: J43.11 96.77,17.71 96.77,19.19 97.87,20.29 97.87,23.94 97.16,24.65 97.16,42.03 108.84,53.7 116.51,53.7 118.97,56.17 120.44,56.17 124.61,60.33 124.61,63.41 127.17,65.97 127.17,70.19 128.88,71.89 128.88,73.72 130.63,75.47 130.63,77.56 134.01,80.93 134.01,81.49 134.97,82.46 143.18,82.46 145.04,80.59 145.63,80.59 146.94,79.28 146.94,78.39 v1(146.45,77.9)
CAMERA_SP4: length 5.3
  TOP w0.191: TP217.1 148.61,59.04 149.12,59.04 149.49,58.67 J503.4
COIL_AOUT1: length 39.6
  TOP w0.279: C134.1 163.31,41.78 166.63,38.46 171.42,38.46 174.54,35.35 J17.1
  TOP w0.432: C134.1 162.22,41.91 161.29,42.84 J14.1 158.66,45.09 155.45,41.87 U35.2
COIL_AOUT2: length 40.9
  TOP w0.279: C134.2 164.35,41.43 166.83,38.95 172.92,38.95 176.02,35.85 J17.2
  TOP w0.432: U35.4 155.4,43.17 158.97,46.74 162.67,46.74 163.29,46.12 J14.2 163.29,43.89 164.35,42.82 C134.2
COIL_BOUT1: length 41.5
  TOP w0.279: J17.3 176.79,36.35 173.76,39.38 167.05,39.38 165.21,41.22 C135.1
  TOP w0.432: C135.1 165.24,41.94 165.24,42.88 165.73,43.37 J15.1 163.27,47.55 157.67,47.55 155.24,45.12 U35.7
COIL_BOUT2: length 43.7
  TOP w0.191: J17.4 177.23,36.85 177.06,37.02 ; U35.5 v1(153.48,43.82)
  TOP w0.279: C135.2 166.26,41.27 167.66,39.86 174.21,39.86 177.06,37.02
  TOP w0.432: J15.2 167.73,42.6 167.04,41.91 C135.2
  BOTTOM w0.191: J15.2 167.73,46.25 167.17,46.81 158.64,46.81 155.65,43.82 v1(153.48,43.82)
CW0_INDEX: length 77.1
  TOP w0.191: v1(125.07,126.58) 125.55,127.06 128.09,127.06 128.79,126.36 R872.1 128.79,120.95 128.37,120.53 TP278.1 ; U15.AE29 161.45,102.9 161.45,103.6 162.51,104.66 165.81,104.66 166.1,104.95 166.1,108.96 164.16,110.91 164.16,111.72 163.55,112.33 156.18,112.33 152.39,116.12 v1(152.39,117.23)
  BOTTOM w0.191: TP278.1 128.37,118.6 130.35,116.62 130.35,115.66 132.33,113.67 140.25,113.67 140.92,113.01 144.95,113.01 146.38,114.44 146.38,116.67 146.94,117.23 v1(152.39,117.23) ; R875.1 122.24,126.06 122.76,126.58 v1(125.07,126.58) U538.1
CW0_PWM_OUT: length 204.9
  TOP w0.191: TP241.1 56.2,62.86 R777.2 ; v1(154.38,121.37) 151.71,118.7 151.71,115.07 154.17,112.61 154.17,111.67 155.9,109.94 160.85,109.94 161.13,109.66 161.13,106.08 161.82,105.39 161.82,104.46 161.06,103.7 161.06,103.51 U15.AE30
  LY12 w0.122: TP241.1 55.56,65.53 67.99,77.96 67.99,98.92 71.95,102.88 71.95,108.42 70.84,109.53 70.84,112.99 v1(77.19,119.34)
  BOTTOM w0.191: v1(154.38,121.37) 154.38,128.3 152.09,130.59 137.13,130.59 131.77,135.95 105.23,135.95 102.23,138.95 90.04,138.95 89.3,139.68 88.46,139.68 87.8,139.02 87.09,139.02 86.43,139.68 85.62,139.68 84.4,138.46 84.4,133.52 84.9,133.02 84.9,131.84 84.62,131.56 84.62,131.54 83.83,130.76 83.83,118.64 83.6,118.41 80.83,118.41 80.34,117.92 78.61,117.92 v1(77.19,119.34)
CW1_INDEX: length 88.8
  TOP w0.191: v1(146.45,112.33) 145.73,111.61 R866.1 ; v1(96.44,124.6) 102.42,124.6 TP280.1
  LY12 w0.122: TP280.1 102.15,124.86 102.15,127.44 100.02,129.57 100.02,133.49 100.94,134.4 v1(101.34,134.4)
  BOTTOM w0.191: R613.1 146.63,112.51 v1(146.45,112.33) 146.17,112.61 140.85,112.61 140.79,112.67 140.77,112.67 140.18,113.27 131.92,113.27 127.58,117.61 127.58,120 127,120.58 122.63,120.58 118.84,124.37 118.84,125.46 110.69,133.61 105.36,133.61 104.57,134.4 v1(101.34,134.4) ; R879.1 103.82,123.19 TP280.1 102.59,124.42 99.31,124.42 99.07,124.18 U566.7 ; v1(96.44,124.6) 96.2,124.83 R876.1
CW1_PWM_OUT: length 283.9
  TOP w0.191: U15.K28 v1(145.45,101.9)
  LY3 w0.122: v1(145.45,101.9) 145.89,102.34 145.89,103.16 145.64,103.41 144.42,103.41 143.86,103.97 143.86,109.99 142.85,111.01 142.85,112.35 142.29,112.91 140.69,112.91 139.29,114.31 139.29,126.37 134.87,130.79 134.87,131.73 127.64,138.96 127.64,142.19 128.27,142.81 128.27,144.53 125.83,146.97 104.75,146.97 103.86,147.86 90.24,147.86 85.85,143.47 80.36,143.47 77.85,145.98 72.08,145.98 70.71,147.35 48,147.35 46.33,149.03 16.48,149.03 2.33,134.88 2.33,58.58 8.84,52.07 TP242.1
  BOTTOM w0.191: TP242.1 16.62,52.07 R798.2
CW2_INDEX: length 37.4
  TOP w0.191: R868.1 151.51,111.01 TP282.1 ; R880.1 133.63,104.53 v1(132.38,104.53)
  BOTTOM w0.191: U539.1 130.79,108.88 130.43,108.52 130.43,107.53 130.3,107.4 129.74,107.4 R883.1 129.65,105.1 130.22,104.53 v1(132.38,104.53) 133.24,104.53 133.52,104.81 133.52,107.25 134.45,108.17 139.91,108.17 140.24,108.5 140.94,108.5 141.91,109.47 141.91,110.44 142.35,110.89 148.01,110.89 149.63,112.51 R601.1 151.19,112.13 TP282.1
CW2_PWM_OUT: length 118.7
  TOP w0.191: U15.K29 145.93,102.4 145.45,102.88 v1(145.45,102.9)
  LY3 w0.076: 142.99,99.68 142.79,99.49 139.69,99.49 139.69,99.49 139.2,99.49 139.2,99.49 137.26,99.49 137.25,99.5 137.09,99.5 137.08,99.48 136.74,99.48
  LY3 w0.102: v1(145.45,102.9) 145.45,102.88 144.95,102.39 144.95,100.52 144.85,100.42 143.25,100.42 142.99,100.15 142.99,99.68 ; 135.88,99.97 136.23,99.97 136.39,99.81 136.41,99.81 136.74,99.48
  LY3 w0.122: TP243.1 52.8,95.67 52.8,99.32 57.27,103.79 60.22,103.79 68.07,111.64 80.03,111.64 81.81,109.86 89.05,109.86 98.32,100.59 107.29,100.59 108.47,99.41 120.41,99.41 120.99,99.41 121.33,99.07 123.16,99.07 123.44,99.35 133.5,99.35 134.12,99.97 135.88,99.97
  BOTTOM w0.191: TP243.1 52.45,95.31 52.45,95.41 52.92,95.89 R819.2
CY_GPIO_0: length 31.6
  TOP w0.191: U562.25 28.75,76.36 v1(29.03,76.08) ; v1(46.3,91.04) 45.9,91.44 U42.2
  BOTTOM w0.191: v1(46.3,91.04) 45.06,91.04 44.14,90.13 44.14,86.39 43.02,85.28 43.02,82.99 42.08,82.05 37.92,82.05 36.04,80.17 36.04,79.18 34.44,77.58 31.29,77.58 30.89,77.98 29.79,77.98 29.55,77.74 29.55,76.61 v1(29.03,76.08)
CY_GPIO_0_DRV: length 2.7
  TOP w0.191: U42.4 43.23,92.08 v1(41.92,92.08)
  BOTTOM w0.191: R226.2 v1(41.92,92.08)
CY_GPIO_0_LED: length 2.6
  TOP w0.191: v1(37.6,92.08) D10.1
  BOTTOM w0.191: R226.1 v1(37.6,92.08)
CY_GPIO_1: length 25.9
  TOP w0.191: v1(30.19,77.3) 29.94,77.3 29.5,76.86 29.2,76.86 29.2,76.85 28.78,76.85 U562.26 ; v1(46.02,87.26) 45.65,87.63 U40.2
  BOTTOM w0.191: v1(46.02,87.26) 43.51,84.74 43.51,82.89 42.08,81.47 38.12,81.47 36.75,80.1 36.75,79.35 34.65,77.25 34.59,77.25 34.58,77.24 31.15,77.24 31.08,77.3 v1(30.19,77.3)
CY_GPIO_1_DRV: length 2.4
  TOP w0.191: U40.4 42.92,88.27 v1(41.64,88.27)
  BOTTOM w0.191: R218.2 v1(41.64,88.27)
CY_GPIO_1_LED: length 2.4
  TOP w0.191: D53.1 v1(37.71,88.27)
  BOTTOM w0.191: v1(37.71,88.27) R218.1
CY_GPIO_2: length 23.8
  TOP w0.191: U562.27 v1(28.99,77.36)
  LY12 w0.122: J96.3 36.39,94.5 36.39,88.1 35.48,87.18 33.47,87.18 32.51,86.22 32.51,81.87 31.37,80.73 31.37,79.84 28.99,77.47 v1(28.99,77.36)
CY_GPIO_5: length 20.3
  TOP w0.191: v1(29.71,79.16) 29.41,78.85 U562.30
  LY12 w0.122: v1(29.71,79.16) 30.35,79.79 30.35,81.03 32.1,82.79 32.1,86.45 33.3,87.64 33.3,93.94 J96.4
CY_GPIO_6: length 47.8
  TOP w0.191: v1(28.79,79.45) 28.7,79.35 U562.31 ; U564.2 45.55,83.82 v1(46.12,83.24)
  LY3 w0.122: v1(28.79,79.45) 28.79,79.38 29.56,78.62 31.31,78.62 32.05,79.35 41.58,79.35 43.53,77.4 45.77,77.4 47.19,78.83 47.19,82.18 v1(46.12,83.24)
  LY12 w0.122: J96.5 30.7,93.89 30.7,87.16 30.15,86.6 28.04,86.6 27.1,85.66 27.1,83.02 28.42,81.7 28.42,79.76 28.73,79.45 v1(28.79,79.45)
CY_GPIO_6_BUF: length 2
  TOP w0.191: U564.4 v1(42.11,84.47)
  BOTTOM w0.191: v1(42.11,84.47) 42.09,84.45 R217.1
CY_GPIO_7: length 25.1
  TOP w0.191: U562.32 27.64,79.84 28.29,79.84 v1(29.1,80.64) U563.2
  LY12 w0.122: v1(29.1,80.64) 29.1,81.43 29.54,81.87 29.54,85.56 31.03,87.05 31.03,92.62 33.24,94.83 33.24,96.22 32.86,96.61 30.88,96.61 J96.6
CY_GPIO_7_BUF: length 2.3
  TOP w0.191: v1(33.46,79.9) 32.42,79.9 U563.4
  BOTTOM w0.191: R212.1 v1(33.46,79.9)
CY_GPIO_8: length 23.2
  TOP w0.191: TP129.1 44.77,76.95 R154.2 ; v1(27.63,81.75) 26.77,81.75 26.33,81.31 U562.2
  LY3 w0.122: TP129.1 42.37,80.01 41.86,80.53 33.19,80.53 31.97,81.75 v1(27.63,81.75)
CY_GPIO_9: length 7.1
  TOP w0.191: U562.3 25.83,81.37 25.69,81.51 25.69,82.25 26.2,82.75 27.19,82.75 J84.1
  BOTTOM w0.191: J84.1 28.26,84.98 R219.2
CY_GPIO_10: length 14.5
  TOP w0.191: v1(26.52,83.75) 24.94,82.17 24.87,82.17 24.58,81.88 24.58,81.46 24.83,81.21 U562.5
  LY3 w0.122: J75.2 31.44,85.1 27.07,85.1 26.52,84.54 v1(26.52,83.75)
CY_GPIO_11: length 13
  TOP w0.191: v1(24.43,82.46) 24.43,82.33 24.3,82.2 24.3,82.08 24.24,82.02 24.24,81.32 24.3,81.25 24.3,80.68 U562.6
  LY3 w0.122: v1(24.43,82.46) 24.91,82.46 25.29,82.84 25.29,84.59 26.26,85.56 29.36,85.56 J75.4
CY_GPIO_12: length 18.9
  TOP w0.191: U562.7 23.83,81.56 v1(23.74,81.65)
  LY3 w0.122: v1(23.74,81.65) 23.72,81.67 23.72,83.02 24.71,84.01 24.71,84.84 26.11,86.24 27.5,86.24 J75.6
  LY12 w0.122: J96.7 26.99,92.93 28.22,91.7 28.22,89.58 J75.6
CY_GPIO_13: length 17.5
  TOP w0.191: U562.8 23.33,81.22 23.24,81.31 23.24,81.44 23.23,81.45 23.23,81.86 23.24,81.86 23.24,81.97 24.3,83.03 24.55,83.03 v1(24.81,83.3) 24.81,86.09 25.7,86.98 25.7,94 J96.8
  BOTTOM w0.191: v1(24.81,83.3) 25.45,83.93 R211.1
CY_GPIO_13_T: length 3.8
  BOTTOM w0.191: R211.2 25.72,87 J75.8
CY_GPIO_14: length 17.2
  TOP w0.191: J75.10 24.45,86.74 24.3,86.6 24.3,83.55 22.54,81.78 U562.9
  LY12 w0.122: J75.10 21.91,90.8 J96.9
CY_GPIO_16: length 9.6
  TOP w0.191: U562.13 20.6,77.86 18.21,80.25 18.21,84.34 TP145.1
CY_GPIO_17: length 33.8
  TOP w0.191: U562.21 25.33,74.74 25.33,74.74 25.33,74.54 25.33,74.54 25.33,74.32 25.25,74.24 v1(25.25,73.69)
  LY12 w0.122: v1(25.25,73.69) 25.95,72.99 25.95,72.22 26.41,71.76 27.94,71.76 29,72.83 29,75.25 25.53,78.72 25.53,81.45 25.55,81.48 25.55,81.86 25.53,81.89 25.53,85.32 23.19,87.66 23.19,88.71 19.37,92.52 J96.10
CY_GPIO_18: length 30.4
  LY12 w0.122: v1(28.09,73.9) 28.09,75.37 22.65,80.81 22.65,81.9 24.81,84.06 24.81,85.38 22.91,87.28 22.91,88.59 19.09,92.41 19.09,92.99 J96.11
  BOTTOM w0.191: v1(28.09,73.9) 26.7,72.5 R222.2
CY_GPIO_18_T: length 2.1
  TOP w0.191: U562.22 v1(25.83,74.33)
  BOTTOM w0.191: R222.1 26.03,73.98 25.83,74.18 v1(25.83,74.33)
CY_IIC0_OE: length 9.3
  TOP w0.191: J84.2 32.29,83.82 32.83,84.36 33.52,84.36 33.82,84.07 U561.6
  BOTTOM w0.191: R155.2 32.18,85.2 J84.2 30.8,84.98 R219.1
CY_IIC0_SCL: length 26.9
  TOP w0.191: U560.6 34,78.74 v1(33.44,78.18) 33.11,77.86 29.2,77.86 29.2,77.86 28.78,77.86 28.78,77.86 U562.28 ; v1(37.94,75.24) 39.04,75.24 39.26,75.02 U27.8 ; U561.8 35.05,83.06 35.98,83.06 36.72,82.32 v1(36.72,81.92)
  LY3 w0.122: v1(37.94,75.24) 35.01,78.18 v1(33.44,78.18)
  LY12 w0.122: v1(37.94,75.24) 37.94,80.69 v1(36.72,81.92)
  BOTTOM w0.191: R605.1 v1(36.72,81.92)
CY_IIC0_SDA: length 23
  TOP w0.191: U561.1 38.05,83.01 39.33,83.01 39.8,82.54 R623.1 38.77,81.92 36.79,79.93 ; 36.79,79.93 35.37,79.93 U560.5 35.05,79.76 34.35,79.76 33.95,79.36 30.93,79.36 29.93,78.35 U562.29 ; 36.79,79.93 37.07,79.65 37.07,75.49 36.31,74.73 U27.1
CY_IIC_MSP_OE: length 6.7
  TOP w0.191: R154.1 40.96,74.18 40.96,72.97 40.76,72.78 U27.6
CY_MSP_SCL: length 94.8
  TOP w0.191: U27.5 v1(38.05,72.28) ; v1(20.62,112.89) 20.19,112.46 U26.38
  LY12 w0.122: v1(20.62,112.89) 19.2,112.89 17.88,114.21 15.13,114.21 13.38,112.45 4.39,112.45 1.55,109.61 1.55,82.81 15.24,69.12 33.5,69.12 36.7,72.32 38,72.32 v1(38.05,72.28)
CY_MSP_SDA: length 84.1
  TOP w0.191: v1(34.74,71.64) 35.38,72.28 U27.4 ; U26.37 18.98,112.99 v1(16.61,112.99)
  LY12 w0.122: v1(16.61,112.99) 15.57,111.95 5.23,111.95 2.54,109.25 2.54,82.22 12.46,72.3 25.4,72.3 26.74,70.95 29.28,70.95 29.97,71.64 v1(34.74,71.64)
CY_SUSPEND: length 11.9
  TOP w0.191: TP144.1 20.75,85.61 20.75,79.61 21.51,78.85 U562.11
CY_VBUS: length 13.4
  TOP w0.191: J83.1 16.89,72.96 23.72,72.96 24.09,73.33 v1(24.09,74.27) 24.09,74.37 24.33,74.6 24.33,74.74 24.33,74.75 U562.19
  BOTTOM w0.191: C625.1 24.45,74.04 24.22,74.27 v1(24.09,74.27)
CY_VCCD: length 2.3
  TOP w0.191: U562.16 22.53,76.36 21.74,76.36 21.48,76.1 C624.1
CY_WAKEUP: length 17.2
  TOP w0.191: TP147.1 15.57,86.34 19.48,86.34 20.37,85.45 20.37,82.91 19.99,82.53 19.99,79.23 20.86,78.35 U562.12
DAC_EN0Z: length 35.9
  TOP w0.191: J122.1 153.64,34.58 150.03,34.58 148.79,33.33 144.06,33.33 142.56,31.83 TP209.1 142.56,30.56 142.08,30.08 135.56,30.08 134.72,30.92 134.72,33.38 133.93,34.17 131.57,34.17 131.2,33.81 U51.19
DAC_EN1Z: length 29.9
  TOP w0.191: U51.20 131.7,29.9 132.05,29.55 146.71,29.55 TP211.1 148.91,31.78 151.15,34.02 154.58,34.02 J122.2
DAO_CLKOUT: length 174.9
  TOP w0.185: J500.42 67.37,9.9 v1(67.58,10.11)
  LY5 w0.122: v1(67.58,10.11) 67.58,10.91 69.98,13.31 74.35,13.31 75.01,12.66 75.21,12.66 78.23,15.68 87.14,15.68 87.82,16.35 89.77,16.35 95.91,22.49 95.91,54.44 95.07,55.28 95.07,69.99 100.45,75.37 100.45,90.86 108.3,98.71 128.89,98.71 135.77,105.6 137.54,105.6 138.69,106.75 150.02,106.75 150.82,107.55 150.82,115.36 v1(150.09,116.09)
  BOTTOM w0.191: R678.1 v1(150.09,116.09)
DAO_DO_0: length 164.8
  TOP w0.185: v1(65.72,9.86) 65.37,9.51 J500.38
  TOP w0.191: R676.1 v1(141.92,111.9)
  LY5 w0.122: v1(65.72,9.86) 63.48,9.86 60.47,12.86 60.47,31.66 64.61,35.8 64.61,41.13 76.53,53.04 76.53,54.92 81.28,59.67 81.28,71.54 85.19,75.45 85.19,83.45 96.11,94.37 96.11,101.18 105.96,111.03 121.43,111.03 124.33,113.93 133.52,113.93 134.16,113.29 140.53,113.29 v1(141.92,111.9)
DAO_DO_1: length 177.2
  TOP w0.185: v1(66.76,9.83) 66.37,9.44 J500.40
  LY5 w0.122: v1(66.76,9.83) 66.76,10.49 70.3,14.03 71.93,14.03 72.56,14.66 76.07,14.66 79.32,17.92 89.61,17.92 95.25,23.55 95.25,53.7 94.2,54.75 94.2,71.08 99.49,76.36 99.49,95.65 103.01,99.17 128.06,99.17 136.06,107.17 148.77,107.17 148.89,107.06 149.25,107.06 149.83,107.64 149.83,108.49 149.17,109.15 149.17,111.34 v1(146.71,113.8)
  BOTTOM w0.191: v1(146.71,113.8) 146.99,114.08 146.99,115.44 R677.1
DMD1_SPARE_43: length 5.4
  TOP w0.191: v1(178.99,72.58) 179.14,72.73 179.85,72.73 179.99,72.6 J10.43
  BOTTOM w0.191: R671.1 178.96,72.55 v1(178.99,72.58) 179.4,72.58 179.74,72.91 R670.1
DMD_DEN_ARSTZ: length 93.8
  TOP w0.191: v1(178.21,122.44) 179.71,122.44 180.03,122.13 J7.43 ; U15.AK12 v1(165.45,84.9)
  BOTTOM w0.191: v1(178.21,122.44) 178.21,123.92 179.02,124.72 183.23,124.72 186.69,121.27 186.69,85.78 184.96,84.06 184.96,78.95 183.99,77.99 183.99,72.48 183.39,71.87 R670.2 180.54,71.87 180.27,71.6 179.42,71.6 179.13,71.89 179.13,71.93 179.09,71.97 174.28,71.97 169.37,76.88 169.37,82.85 168.36,83.86 167.94,83.86 167.47,84.33 167.47,84.85 R120.1 167.07,85.25 165.8,85.25 v1(165.45,84.9)
